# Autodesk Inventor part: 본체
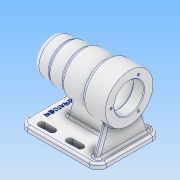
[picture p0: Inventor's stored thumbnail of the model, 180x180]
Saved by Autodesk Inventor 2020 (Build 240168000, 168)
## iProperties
Created: 2021-10
Part Number: 본체
Material: 알루미늄 6061
Document SubType Name: Modeling
Designer: user
Density: 2.7 g/cm^3
Appearance: 알루미늄 - 평지
Mass: 694.197 g
Surface Area: 698.877 cm^2
Volume: 257.11 cm^3
Author: user
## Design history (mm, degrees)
sketch "스케치1"
  geometry: L1 (0, 0)-(24, 0); L2 (24, 0)-(24, 25); L3 (24, 25)-(0, 25); L4 (0, 25)-(0, 0); L5 (24, 0)-(46, 0); L6 (46, 0)-(46, 27); L7 (46, 27)-(24, 27); L8 (24, 27)-(24, 0); L9 (46, 0)-(80, 0); L10 (80, 0)-(80, 30); L11 (80, 30)-(46, 30); L12 (46, 30)-(46, 0); L13 (80, 0)-(112, 0); L14 (112, 0)-(112, 34); L15 (112, 34)-(80, 34); L16 (80, 34)-(80, 0); 3 further points
  constraints: 32 end point, 8 parallel, 4 horizontal, 4 perpendicular
  dimensions: "d0" = 50 diameter of L3 L13; "d1" = 54 diameter of L7 L13; "d2" = 60 diameter of L11 L13; "d3" = 68 diameter of L15 L13; "d17" = 24 distance of L2.end L3.end; "d18" = 46 distance between parallel lines of L4 L12; "d19" = 80 distance between parallel lines of L4 L10; "d20" = 112 distance between parallel lines of L4 L14
revolve "회전1" sketch "스케치1" stored, may be unused: angle "d4" = 90 deg
sketch "스케치2"
  geometry: L1 (112, -34)-(112, 34) reference; L2 (112, 0)-(97, 0); L3 (97, 0)-(97, 21); L4 (97, 21)-(112, 21); L5 (112, 21)-(112, 0); L6 (97, 0)-(43, 0); L7 (43, 0)-(43, 24); L8 (43, 24)-(97, 24); L9 (97, 24)-(97, 0); L10 (43, 0)-(31, 0); L11 (31, 0)-(31, 21); L12 (31, 21)-(43, 21); L13 (43, 21)-(43, 0); L14 (31, 0)-(13, 0); L15 (13, 0)-(13, 17.5); L16 (13, 17.5)-(31, 17.5); L17 (31, 17.5)-(31, 0); L18 (13, 0)-(9, 0); L19 (9, 0)-(9, 16); L20 (9, 16)-(13, 16); L21 (13, 16)-(13, 0); L22 (9, 0)-(6, 0); L23 (6, 0)-(6, 10.5); L24 (6, 10.5)-(9, 10.5); L25 (9, 10.5)-(9, 0); 7 further points
  constraints: 48 end point, 12 parallel, 6 horizontal, 6 perpendicular, 1 midpoint, 1 point on line
  dimensions: "d5" = 42 diameter of L4 L2; "d6" = 15 distance of L3.end L4.end; "d7" = 48 diameter of L8 L2; "d9" = 21 diameter of L24 L2; "d10" = 3 distance of L23.end L24.end; "d11" = 32 diameter of L20 L2; "d12" = 4 distance of L19.end L20.end; "d13" = 35 diameter of L16 L2; "d14" = 18 distance of L15.end L16.end; "d15" = 12 distance of L11.end L12.end; "d16" = 54 distance of L7.end L8.end
revolve "회전2" sketch "스케치2" stored, may be unused: angle "d21" = 90 deg
node "작업 평면1"
sketch "스케치4"
  geometry: L1 (0, 45)-(-112, 45); L2 (-112, 45)-(-112, -45); L3 (-112, -45)-(0, -45); L4 (0, -45)-(0, 45); L5 (0, 45)-(-112, -45); L6 (-112, 45)-(0, -45); L7 (0, 25)-(0, -25) reference; 3 further points
  constraints: 12 end point, 2 midpoint, 2 parallel, 1 coincident, 1 horizontal, 1 perpendicular
  dimensions: "d23" = 112 distance of L2.end L3.end; "d24" = 90 distance of L3.end L1.start; "d25" = 56 distance from line of point (-56, 0) L7; "d26" = 45 distance from line of L3 point (0, 0)
extrude "돌출1" join sketch "스케치4" distance "d27" = 8; taper "d28" = 0 deg
sketch "스케치5"
  geometry: L1 (20, 33)-(35, 33); L2 (20, 28.5)-(35, 28.5); L3 (35, 37.5)-(20, 37.5); L4 (60, 33)-(75, 33); L5 (60, 28.5)-(75, 28.5); L6 (75, 37.5)-(60, 37.5); L7 (0, 0)-(-30.43, 0); L8 (20, -33)-(35, -33); L9 (20, -28.5)-(35, -28.5); L10 (35, -37.5)-(20, -37.5); L11 (60, -33)-(75, -33); L12 (60, -28.5)-(75, -28.5); L13 (75, -37.5)-(60, -37.5); L14 (112, -45)-(112, 45) reference; L15 (0, 45)-(0, -45) reference; A1 r 4.5 centre (20, 33) between (20, 37.5) and (20, 28.5); A2 r 4.5 centre (35, 33) between (35, 28.5) and (35, 37.5); A3 r 4.5 centre (60, 33) between (60, 37.5) and (60, 28.5); A4 r 4.5 centre (75, 33) between (75, 28.5) and (75, 37.5); A5 r 4.5 centre (20, -33) between (20, -28.5) and (20, -37.5); A6 r 4.5 centre (35, -33) between (35, -37.5) and (35, -28.5); A7 r 4.5 centre (60, -33) between (60, -28.5) and (60, -37.5); A8 r 4.5 centre (75, -33) between (75, -37.5) and (75, -28.5); 4 further points
  constraints: 34 end point, 16 point on circle, 14 symmetric about line, 8 centre point, 8 tangent, 4 point on line, 2 horizontal, 2 midpoint, 2 parallel, 4 other
  dimensions: "d29" = 9 distance between parallel lines of L2 L3; "d30" = 15 distance of L1.end L1.start; "d31" = 15 distance of L4.start L4.end; "d32" = 25 distance of L11.start L8.end; "d33" = 66 distance of point (27.5, -33) point (27.5, 33); "d81" = 20 distance from line of L15 L1.start
extrude "돌출2" cut sketch "스케치5" distance "d35" = 12; taper "d36" = 0 deg
sketch "스케치7"
  geometry: L1 (104, -4)-(27, -4); L2 (27, -4)-(27, 4); L3 (27, 4)-(104, 4); L4 (104, 4)-(104, -4); L5 (104, -4)-(27, 4); L6 (27, -4)-(104, 4); L7 (112, 45)-(0, 45) reference; L8 (112, -45)-(112, 45) reference; 3 further points
  constraints: 12 end point, 2 midpoint, 2 parallel, 1 horizontal, 1 perpendicular, 1 point on line
  dimensions: "d37" = 8 distance of L1.end L2.end; "d39" = 8 distance from line of L8 point (104, 45); "d40" = 77 distance from line of L2 point (104, 45); "d41" = 0 distance from line of point (104, 45) L4
extrude "돌출3" join sketch "스케치7" stored distance "d42" = 12; taper "d43" = 0 deg
feature "면 기울기1" dims angle "d44" = 15 deg
sketch "스케치9"
  geometry: L1 (49, 0)-(-41, 0) reference; L2 (-33, 0)-(-19.409, 37.342); L3 (4, 62)-(4, 69.814); L4 (41, 0)-(27.409, 37.342); L5 (49, -8)-(49, 0) reference; L6 (-41, 0)-(49, 0) reference; L7 (0, 0)-(0, 28.236) reference; L8 (8, 0)-(8, 28.236) reference; A1 r 34 centre (4, 62) between (-19.409, 37.342) and (0, 28.236) reference; 3 further points
  constraints: 6 end point, 2 symmetric about line, 1 point on circle, 1 point on line, 1 vertical
  dimensions: "d45" = 8 distance from line of L5 L4.start; "d46" = 110 deg angle of L1 L4
extrude "돌출4" join sketch "스케치9" distance "d47" = 8; taper "d48" = 0 deg
sketch "스케치10" dims "d49" = 52
  geometry: C1 r 10.5 at (0, 0) reference; 3 further points
  constraints: 1 coincident, 1 horizontal alignment, 2 other
hole "구멍1" sketch "스케치10" at (-26, 0) diameter "d50" = 3.242; stored, may be unused: countersink angle "d54" = 90 deg, drill point angle "d56" = 118 deg; dims "d51" = 8, "d52" = 4, "d53" = 2, "d55" = 11
fillet "모깎기1" dims "d60" = 0.3
fillet "모깎기2" dims "d61" = 3
fillet "모깎기3" dims "d62" = 3
chamfer "모따기1" distance "d63" = 1; stored, may be unused: second distance "d64" = 2, angle "d65" = 45 deg
fillet "모깎기4" dims "d66" = 8
fillet "모깎기5" dims "d67" = 12
fillet "모깎기6" dims "d68" = 3
fillet "모깎기7" dims "d69" = 3
fillet "모깎기8" dims "d70" = 3
sketch "스케치13"
  geometry: L1 (0, 33)-(0, -33) reference; 2 further points
  constraints: 1 other
  dimensions: "d78" = 12 distance from line of L1 point (12, -0.117)
fillet "모깎기11" dims "d76" = 3
fillet "모깎기12" dims "d77" = 3
feature "엠보싱1" dims "d0" = 50, "d1" = 54, "d2" = 60, "d3" = 68, "d17" = 24, "d18" = 46, "d19" = 80, "d20" = 112, "d79" = 0.5, "d80" = 0
node "솔리드1"
pattern_circular "원형 패턴1" dims angle "d58" = 360 deg
